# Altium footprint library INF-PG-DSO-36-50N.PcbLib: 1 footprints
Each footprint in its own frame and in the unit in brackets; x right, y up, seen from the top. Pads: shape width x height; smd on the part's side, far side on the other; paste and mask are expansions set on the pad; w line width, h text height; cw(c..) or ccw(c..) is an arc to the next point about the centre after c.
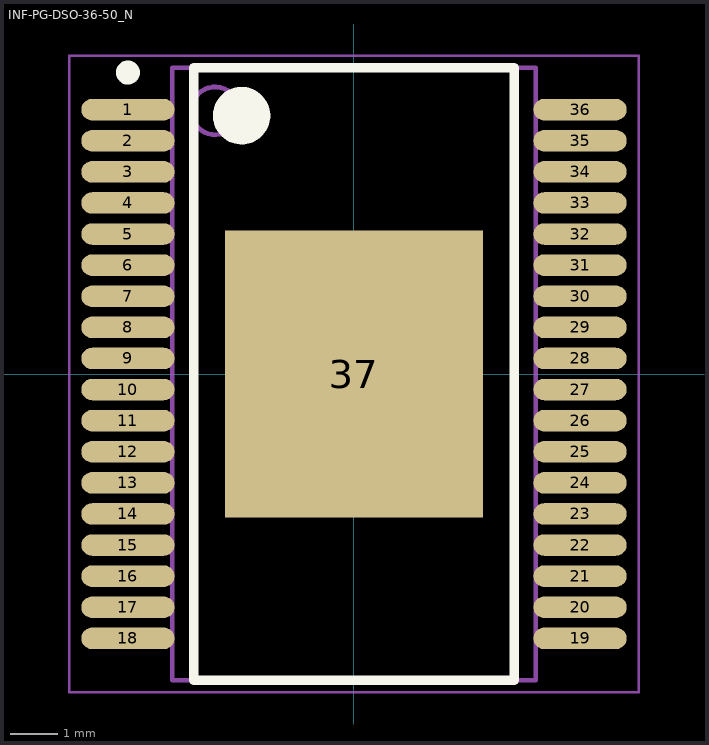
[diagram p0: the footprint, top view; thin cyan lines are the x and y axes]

## INF-PG-DSO-36-50_N [mm] "SOP, 36-Leads, Body 12.7x7.5mm, Pitch 0.65mm, Thermal Pad 6000x5400mm, IPC Medium Density"
height 2.55
pads (37):
  oval 1.95x0.45 smd: 1(-4.725,5.525) 2(-4.725,4.875) 3(-4.725,4.225) 4(-4.725,3.575) 5(-4.725,2.925) 6(-4.725,2.275) 7(-4.725,1.625) 8(-4.725,0.975) 9(-4.725,0.325) 10(-4.725,-0.325) 11(-4.725,-0.975) 12(-4.725,-1.625) 13(-4.725,-2.275) 14(-4.725,-2.925) 15(-4.725,-3.575) 16(-4.725,-4.225) 17(-4.725,-4.875) 18(-4.725,-5.525) 19(4.725,-5.525) 20(4.725,-4.875) 21(4.725,-4.225) 22(4.725,-3.575) 23(4.725,-2.925) 24(4.725,-2.275) 25(4.725,-1.625) 26(4.725,-0.975) 27(4.725,-0.325) 28(4.725,0.325) 29(4.725,0.975) 30(4.725,1.625) 31(4.725,2.275) 32(4.725,2.925) 33(4.725,3.575) 34(4.725,4.225) 35(4.725,4.875) 36(4.725,5.525)
  rect 5.4x6 smd: 37(0,0)
Top Overlay:
  circle w0.6: c-2.35,5.4 r0.3
  circle w0.25: c-4.725,6.3 r0.125
  lines w0.2: -3.35,-6.4 3.35,-6.4 3.35,6.4 -3.35,6.4 -3.35,-6.4
Mechanical 13:
  circle w0.1: c-2.9,5.5 r0.5
  lines w0.1: -3.8,-6.4 3.8,-6.4 3.8,6.4 -3.8,6.4 -3.8,-6.4
Mechanical 15:
  lines w0.05: -5.95,-6.65 5.95,-6.65 5.95,6.65 -5.95,6.65 -5.95,-6.65
  lines w0.1: -0.5,0 0.5,0 ; 0,-0.5 0,0.5
3D body: height 2.55, standoff 0, extent -3.8,-6.4 3.8,6.4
